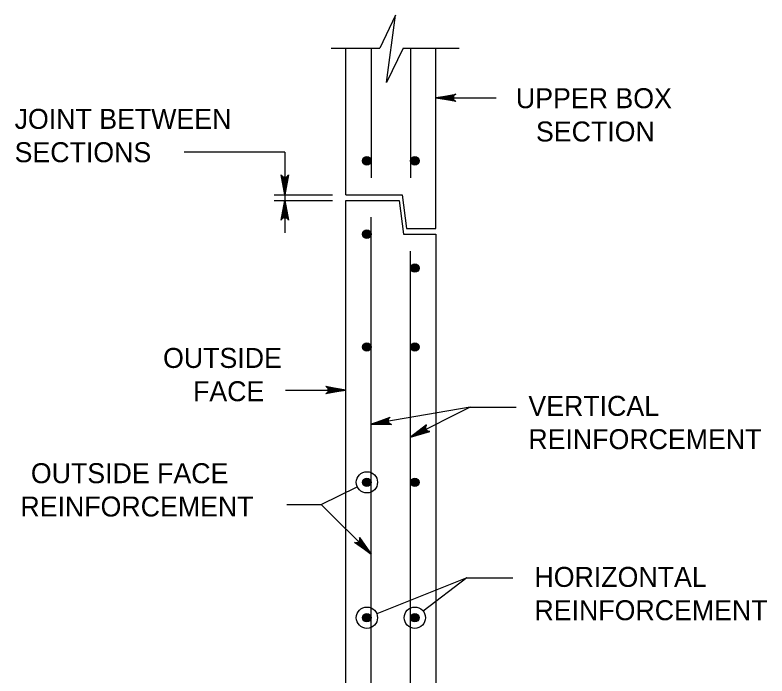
# Model space of a CAD drawing. Extents: x -6420 to 49575, y -4552 to 11624.
# Drawn here: x 2908.7 to 3279, y 2588.7 to 2914.2 of the extents above; entities that cross this region are included whole.
import ezdxf

# ---------------------------------------------------------------- set-up
doc = ezdxf.new("R2010")
doc.units = 0
doc.layers.add('1', color=7, linetype='Continuous')

msp = doc.modelspace()

# ---------------------------------------------------------------- linework, layer by layer
at = {"layer": '1'}
for p, q in [((3064.37, 2897.95), (3088.33, 2897.95)), ((3071.54, 2825.73), (3071.54, 2897.95)), ((3084.04, 2897.95), (3084.04, 2834.07)), ((3099.88, 2897.95), (3127.46, 2897.95)), ((3103.49, 2897.95), (3103.49, 2834.07)), ((3115.99, 2809.07), (3115.99, 2897.95)), ((3115.99, 2873.48), (3145.68, 2873.48)), ((3041.54, 2846.7), (2992.02, 2846.7)), ((3041.54, 2846.7), (3041.54, 2806.99)), ((3036.36, 2825.73), (3065.03, 2825.73)), ((3071.54, 2825.73), (3099.32, 2825.73)), ((3099.32, 2825.73), (3101.4, 2809.07)), ((3036.36, 2822.95), (3065.03, 2822.95)), ((3071.54, 2289.62), (3071.54, 2822.95)), ((3071.54, 2822.95), (3097.93, 2822.95)), ((3097.93, 2822.95), (3100.01, 2806.29)), ((3084.04, 2310.45), (3084.04, 2814.62)), ((3101.4, 2809.07), (3115.99, 2809.07)), ((3100.01, 2806.29), (3115.99, 2806.29)), ((3115.99, 2806.29), (3115.99, 2334.07)), ((3103.49, 2303.51), (3103.49, 2797.95)), ((3041.85, 2729.53), (3071.54, 2729.53)), ((3132.9, 2721.16), (3084.04, 2712.76)), ((3132.9, 2721.16), (3103.45, 2706.28)), ((3132.9, 2721.16), (3155.54, 2721.16)), ((3059.48, 2673.18), (3077.24, 2681.78)), ((3081.96, 2684.07), (3081.96, 2684.07)), ((3042.46, 2673.18), (3059.48, 2673.18)), ((3084.04, 2648.76), (3059.48, 2673.18)), ((3131.15, 2637.09), (3086.83, 2619.35)), ((3131.15, 2637.09), (3109.73, 2620.6)), ((3131.15, 2637.09), (3153.8, 2637.09)), ((3081.96, 2617.4), (3081.96, 2617.4)), ((3105.57, 2617.4), (3105.57, 2617.4))]:
    msp.add_line(p, q, dxfattribs=at)
for points in [[(3099.88, 2897.95), (3091.55, 2880.94), (3096.08, 2914.24), (3088.33, 2897.95)], [(3115.99, 2873.48), (3125.77, 2875.31), (3125.4, 2875.05), (3125.02, 2874.79), (3124.83, 2874.46), (3124.63, 2874.13), (3124.58, 2873.81), (3124.52, 2873.48), (3124.58, 2873.15), (3124.63, 2872.82), (3124.83, 2872.49), (3125.02, 2872.16), (3125.4, 2871.9), (3125.77, 2871.64), (3115.99, 2873.48), (3125.4, 2871.9), (3125.02, 2872.16), (3115.99, 2873.48), (3124.83, 2872.49), (3124.63, 2872.82), (3115.99, 2873.48), (3124.58, 2873.15), (3124.52, 2873.48), (3115.99, 2873.48), (3124.58, 2873.81), (3124.63, 2874.13), (3115.99, 2873.48), (3124.83, 2874.46), (3125.02, 2874.79), (3115.99, 2873.48), (3125.4, 2875.05)], [(3041.54, 2825.73), (3039.71, 2835.52), (3039.97, 2835.14), (3040.23, 2834.76), (3040.56, 2834.57), (3040.89, 2834.38), (3041.21, 2834.32), (3041.54, 2834.26), (3041.87, 2834.32), (3042.2, 2834.38), (3042.53, 2834.57), (3042.85, 2834.76), (3043.12, 2835.14), (3043.38, 2835.52), (3041.54, 2825.73), (3043.12, 2835.14), (3042.85, 2834.76), (3041.54, 2825.73), (3042.53, 2834.57), (3042.2, 2834.38), (3041.54, 2825.73), (3041.87, 2834.32), (3041.54, 2834.26), (3041.54, 2825.73), (3041.21, 2834.32), (3040.89, 2834.38), (3041.54, 2825.73), (3040.56, 2834.57), (3040.23, 2834.76), (3041.54, 2825.73), (3039.97, 2835.14)], [(3041.54, 2822.95), (3043.38, 2813.17), (3043.12, 2813.54), (3042.85, 2813.92), (3042.53, 2814.12), (3042.2, 2814.31), (3041.87, 2814.37), (3041.54, 2814.42), (3041.21, 2814.37), (3040.89, 2814.31), (3040.56, 2814.12), (3040.23, 2813.92), (3039.97, 2813.54), (3039.71, 2813.17), (3041.54, 2822.95), (3039.97, 2813.54), (3040.23, 2813.92), (3041.54, 2822.95), (3040.56, 2814.12), (3040.89, 2814.31), (3041.54, 2822.95), (3041.21, 2814.37), (3041.54, 2814.42), (3041.54, 2822.95), (3041.87, 2814.37), (3042.2, 2814.31), (3041.54, 2822.95), (3042.53, 2814.12), (3042.85, 2813.92), (3041.54, 2822.95), (3043.12, 2813.54)], [(3071.54, 2729.53), (3061.76, 2727.69), (3062.13, 2727.96), (3062.51, 2728.22), (3062.7, 2728.55), (3062.9, 2728.87), (3062.96, 2729.2), (3063.01, 2729.53), (3062.96, 2729.86), (3062.9, 2730.19), (3062.7, 2730.51), (3062.51, 2730.84), (3062.13, 2731.1), (3061.76, 2731.36), (3071.54, 2729.53), (3062.13, 2731.1), (3062.51, 2730.84), (3071.54, 2729.53), (3062.7, 2730.51), (3062.9, 2730.19), (3071.54, 2729.53), (3062.96, 2729.86), (3063.01, 2729.53), (3071.54, 2729.53), (3062.96, 2729.2), (3062.9, 2728.87), (3071.54, 2729.53), (3062.7, 2728.55), (3062.51, 2728.22), (3071.54, 2729.53), (3062.13, 2727.96)], [(3084.04, 2712.76), (3093.38, 2716.22), (3093.05, 2715.9), (3092.72, 2715.58), (3092.59, 2715.22), (3092.45, 2714.87), (3092.45, 2714.54), (3092.45, 2714.2), (3092.56, 2713.89), (3092.67, 2713.57), (3092.92, 2713.28), (3093.17, 2712.99), (3093.58, 2712.8), (3094, 2712.61), (3084.04, 2712.76), (3093.58, 2712.8), (3093.17, 2712.99), (3084.04, 2712.76), (3092.92, 2713.28), (3092.67, 2713.57), (3084.04, 2712.76), (3092.56, 2713.89), (3092.45, 2714.2), (3084.04, 2712.76), (3092.45, 2714.54), (3092.45, 2714.87), (3084.04, 2712.76), (3092.59, 2715.22), (3092.72, 2715.58), (3084.04, 2712.76), (3093.05, 2715.9)], [(3103.45, 2706.28), (3113.01, 2709.06), (3112.56, 2709.12), (3112.11, 2709.19), (3111.78, 2709.39), (3111.46, 2709.6), (3111.26, 2709.86), (3111.07, 2710.13), (3110.97, 2710.45), (3110.87, 2710.77), (3110.9, 2711.15), (3110.92, 2711.53), (3111.14, 2711.93), (3111.36, 2712.33), (3103.45, 2706.28), (3111.14, 2711.93), (3110.92, 2711.53), (3103.45, 2706.28), (3110.9, 2711.15), (3110.87, 2710.77), (3103.45, 2706.28), (3110.97, 2710.45), (3111.07, 2710.13), (3103.45, 2706.28), (3111.26, 2709.86), (3111.46, 2709.6), (3103.45, 2706.28), (3111.78, 2709.39), (3112.11, 2709.19), (3103.45, 2706.28), (3112.56, 2709.12)], [(3084.04, 2648.76), (3075.81, 2654.36), (3076.26, 2654.28), (3076.71, 2654.2), (3077.08, 2654.3), (3077.45, 2654.39), (3077.72, 2654.58), (3077.99, 2654.78), (3078.19, 2655.05), (3078.38, 2655.32), (3078.47, 2655.69), (3078.56, 2656.06), (3078.48, 2656.51), (3078.4, 2656.96), (3084.04, 2648.76), (3078.48, 2656.51), (3078.56, 2656.06), (3084.04, 2648.76), (3078.47, 2655.69), (3078.38, 2655.32), (3084.04, 2648.76), (3078.19, 2655.05), (3077.99, 2654.78), (3084.04, 2648.76), (3077.72, 2654.58), (3077.45, 2654.39), (3084.04, 2648.76), (3077.08, 2654.3), (3076.71, 2654.2), (3084.04, 2648.76), (3076.26, 2654.28)]]:
    msp.add_lwpolyline(points, dxfattribs=at)
for centre, radius in [((3081.96, 2842.4), 2.08), ((3081.96, 2842.4), 1.94), ((3081.96, 2842.4), 1.79), ((3081.96, 2842.4), 1.64), ((3081.96, 2842.4), 1.49), ((3105.57, 2842.4), 2.08), ((3105.57, 2842.4), 1.94), ((3105.57, 2842.4), 1.79), ((3105.57, 2842.4), 1.64), ((3105.57, 2842.4), 1.49), ((3081.96, 2842.4), 1.34), ((3081.96, 2842.4), 1.2), ((3081.96, 2842.4), 1.05), ((3081.96, 2842.4), 0.9), ((3081.96, 2842.4), 0.752), ((3081.96, 2842.4), 0.604), ((3081.96, 2842.4), 0.456), ((3081.96, 2842.4), 0.308), ((3081.96, 2842.4), 0.16), ((3105.57, 2842.4), 1.34), ((3105.57, 2842.4), 1.2), ((3105.57, 2842.4), 1.05), ((3105.57, 2842.4), 0.9), ((3105.57, 2842.4), 0.752), ((3105.57, 2842.4), 0.604), ((3105.57, 2842.4), 0.456), ((3105.57, 2842.4), 0.308), ((3105.57, 2842.4), 0.16), ((3081.96, 2806.29), 2.08), ((3081.96, 2806.29), 1.94), ((3081.96, 2806.29), 1.79), ((3081.96, 2806.29), 1.64), ((3081.96, 2806.29), 1.49), ((3081.96, 2806.29), 1.34), ((3081.96, 2806.29), 1.2), ((3081.96, 2806.29), 1.05), ((3081.96, 2806.29), 0.9), ((3081.96, 2806.29), 0.752), ((3081.96, 2806.29), 0.604), ((3081.96, 2806.29), 0.456), ((3081.96, 2806.29), 0.308), ((3081.96, 2806.29), 0.16), ((3105.57, 2789.62), 2.08), ((3105.57, 2789.62), 1.94), ((3105.57, 2789.62), 1.79), ((3105.57, 2789.62), 1.64), ((3105.57, 2789.62), 1.49), ((3105.57, 2789.62), 1.34), ((3105.57, 2789.62), 1.2), ((3105.57, 2789.62), 1.05), ((3105.57, 2789.62), 0.9), ((3105.57, 2789.62), 0.752), ((3105.57, 2789.62), 0.604), ((3105.57, 2789.62), 0.456), ((3105.57, 2789.62), 0.308), ((3105.57, 2789.62), 0.16), ((3081.96, 2750.73), 2.08), ((3081.96, 2750.73), 1.94), ((3081.96, 2750.73), 1.79), ((3081.96, 2750.73), 1.64), ((3081.96, 2750.73), 1.49), ((3081.96, 2750.73), 1.34), ((3081.96, 2750.73), 1.2), ((3081.96, 2750.73), 1.05), ((3081.96, 2750.73), 0.9), ((3081.96, 2750.73), 0.752), ((3081.96, 2750.73), 0.604), ((3105.57, 2750.73), 2.08), ((3105.57, 2750.73), 1.94), ((3105.57, 2750.73), 1.79), ((3105.57, 2750.73), 1.64), ((3105.57, 2750.73), 1.49), ((3105.57, 2750.73), 1.34), ((3105.57, 2750.73), 1.2), ((3105.57, 2750.73), 1.05), ((3105.57, 2750.73), 0.9), ((3105.57, 2750.73), 0.752), ((3105.57, 2750.73), 0.604), ((3081.96, 2750.73), 0.456), ((3081.96, 2750.73), 0.308), ((3081.96, 2750.73), 0.16), ((3105.57, 2750.73), 0.456), ((3105.57, 2750.73), 0.308), ((3105.57, 2750.73), 0.16), ((3081.96, 2684.07), 5.25), ((3081.96, 2684.07), 2.08), ((3081.96, 2684.07), 1.94), ((3081.96, 2684.07), 1.79), ((3081.96, 2684.07), 1.64), ((3081.96, 2684.07), 1.49), ((3081.96, 2684.07), 1.34), ((3081.96, 2684.07), 1.2), ((3081.96, 2684.07), 1.05), ((3081.96, 2684.07), 0.9), ((3081.96, 2684.07), 0.752), ((3081.96, 2684.07), 0.604), ((3105.57, 2684.07), 2.08), ((3105.57, 2684.07), 1.94), ((3105.57, 2684.07), 1.79), ((3105.57, 2684.07), 1.64), ((3105.57, 2684.07), 1.49), ((3105.57, 2684.07), 1.34), ((3105.57, 2684.07), 1.2), ((3105.57, 2684.07), 1.05), ((3105.57, 2684.07), 0.9), ((3105.57, 2684.07), 0.752), ((3105.57, 2684.07), 0.604), ((3081.96, 2684.07), 0.456), ((3081.96, 2684.07), 0.308), ((3081.96, 2684.07), 0.16), ((3105.57, 2684.07), 0.456), ((3105.57, 2684.07), 0.308), ((3105.57, 2684.07), 0.16), ((3081.96, 2617.4), 5.25), ((3105.57, 2617.4), 5.25), ((3081.96, 2617.4), 2.08), ((3081.96, 2617.4), 1.94), ((3081.96, 2617.4), 1.79), ((3081.96, 2617.4), 1.64), ((3081.96, 2617.4), 1.49), ((3081.96, 2617.4), 1.34), ((3081.96, 2617.4), 1.2), ((3081.96, 2617.4), 1.05), ((3081.96, 2617.4), 0.9), ((3081.96, 2617.4), 0.752), ((3081.96, 2617.4), 0.604), ((3105.57, 2617.4), 2.08), ((3105.57, 2617.4), 1.94), ((3105.57, 2617.4), 1.79), ((3105.57, 2617.4), 1.64), ((3105.57, 2617.4), 1.49), ((3105.57, 2617.4), 1.34), ((3105.57, 2617.4), 1.2), ((3105.57, 2617.4), 1.05), ((3105.57, 2617.4), 0.9), ((3105.57, 2617.4), 0.752), ((3105.57, 2617.4), 0.604), ((3081.96, 2617.4), 0.456), ((3081.96, 2617.4), 0.308), ((3081.96, 2617.4), 0.16), ((3105.57, 2617.4), 0.456), ((3105.57, 2617.4), 0.308), ((3105.57, 2617.4), 0.16)]:
    msp.add_circle(centre, radius, dxfattribs=at)

# ---------------------------------------------------------------- texts
for s, height, p in [('UPPER BOX', 9.843, (3155.35, 2868.35)), ('JOINT BETWEEN', 9.8425, (2908.48, 2858.16)), ('SECTION', 9.843, (3165.23, 2851.95)), ('SECTIONS', 9.843, (2908.48, 2841.75)), ('OUTSIDE', 9.843, (2981.58, 2740.42)), ('FACE', 9.843, (2996.34, 2724.02)), ('VERTICAL', 9.843, (3161.48, 2716.81)), ('REINFORCEMENT', 9.8425, (3161.48, 2700.41)), ('OUTSIDE FACE', 9.8425, (2916.49, 2683.65)), ('REINFORCEMENT', 9.8425, (2911.34, 2667.24)), ('HORIZONTAL', 9.843, (3164.48, 2632.57)), ('REINFORCEMENT', 9.8425, (3164.48, 2616.16))]:
    msp.add_text(s, height=height, dxfattribs=at).set_placement(p)

doc.saveas('drawing.dxf')
